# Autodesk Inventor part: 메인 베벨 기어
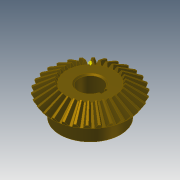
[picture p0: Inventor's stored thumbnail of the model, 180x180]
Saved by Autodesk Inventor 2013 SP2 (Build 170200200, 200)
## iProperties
Created: 2014-10
Part Number: 메인 베벨 기어
Material: Steel, Mild
Document SubType Name: Modeling
Designer: KYOUNG IL JANG
Categories: <?xml version="1.0" encoding="UTF-16"?> <MemberInstance><Categories><FamilyTemplate><FamilyTemplateParameter ValueType="xs:double" Id="1" ObjectReferenceKey="da
Mass: 269.583 g
Surface Area: 108.837 cm^2
Volume: 34.2981 cm^3
Density: 7.86 g/cm^3
CustomPartVersion: 1
Company: 한국ATC센터
Author: KYOUNG IL JANG
Revision Number: 1
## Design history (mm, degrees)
node "맨 위 점"
node "메쉬 평면2"
sketch "톱니 본체 스케치"
  geometry: L1 (0, 0)-(28.669, -21.997); L2 (28.669, -21.997)-(31.109, -18.336); L3 (31.109, -18.336)-(0, 0); L4 (30, -20)-(0, 0); L5 (17.219, -13.212)-(18.685, -11.013); L6 (28.669, -21.997)-(17.219, -13.212); L7 (31.109, -18.336)-(18.685, -11.013); L8 (0, -39.387)-(0, 6.564) reference; L9 (0, -20)-(31.109, -20)
  constraints: 16 end point, 4 point on line, 3 perpendicular, 2 collinear, 1 horizontal alignment, 1 vertical alignment
  dimensions: "d0" = 60 diameter of L4.start L8 (= da_de); "d1" = 57.33744 diameter of L1.end L8 (= da_dfe); "d2" = 62.2188 diameter of L2.end L8 (= da_dae); "d3" = 14.4 distance between parallel lines of L2 L5 (= da_b); "d4" = 18.3359 vertical distance of L2.end L1.start (= da_ve)
revolve "톱니 본체" sketch "톱니 본체 스케치" stored, may be unused: angle "d5" = 90 deg
node "시작점"
node "톱니 평면"
sketch "시작 스케치"
  geometry: L1 (0, -23.505)-(0, 10.645) reference; L2 (-0.709, -2.928)-(0.709, -2.928); A1 r 19.188 centre (-19.457, -7.014) between (-0.709, -2.928) and (-3.232, 3.229); A2 r 19.188 centre (19.457, -7.014) between (3.232, 3.229) and (0.709, -2.928); A3 r 57.403 centre (0, -54.083) between (3.232, 3.229) and (-3.232, 3.229); 1 further point
  constraints: 6 point on circle, 3 centre point, 3 symmetric about line, 2 end point, 1 coincident, 1 perpendicular, 1 other
  dimensions: "d7" = 19.18795 radius of A1 (= fd_rr); "d8" = 19.45712 horizontal distance of point (0, -54.083) A1.centre (= fd_x); "d9" = 47.06905 vertical distance of point (0, -54.083) A1.centre (= fd_y); "d57" = 57.40327 radius of A3 (= 0.5 x fd_dva + 0.3 x da_he); "d58" = 51.15527 distance from line of A3.centre L2 (= 0.5 x fd_dva - 1.12 x da_he)
node "끝점"
  node "끝 평면"
sketch "3D 스케치 오른쪽"
  node "Helical Curve Right" dims "d65" = 229.90621 (computed from da_dm, da_delta, da_beta), "d66" = 31.5, "d67" = 60 (= da_de), "d68" = -9.82794 (= -da_delta), "d69" = 8.10972 (computed from fd_loft, da_delta)
node "끝 평면 오른쪽"
sketch "끝 스케치 오른쪽"
  geometry: L1 (0, -41.54)-(0, 13.178) reference; L2 (-0.422, -1.69)-(0.422, -1.69); A1 r 11.427 centre (-11.587, -4.123) between (-0.422, -1.69) and (-1.925, 1.977); A2 r 11.427 centre (11.587, -4.123) between (1.925, 1.977) and (0.422, -1.69); A3 r 34.184 centre (0, -32.153) between (1.925, 1.977) and (-1.925, 1.977); 1 further point
  constraints: 6 point on circle, 3 centre point, 3 symmetric about line, 2 end point, 1 coincident, 1 perpendicular, 1 other
  dimensions: "d70" = 11.58699 horizontal distance of A3.centre A1.centre (computed from fd_x, fd_ratio); "d71" = 28.03028 vertical distance of point (0, -32.153) A1.centre (computed from fd_y, fd_ratio); "d72" = 11.4267 radius of A1 (computed from fd_rr, fd_ratio); "d73" = 30.46369 distance from line of point (0, -32.153) L2 (computed from d58, fd_ratio); "d74" = 34.18446 radius of A3 (computed from d57, fd_ratio)
feature "로프트 오른쪽" sketch "끝 스케치 오른쪽" dims "d75" = 0, "d77" = 0, "d79" = 0, "d80" = 90 deg, "d85" = 20, "d92" = 90 deg, "d93" = 90 deg, "da_teethtype" = 0 [user parameter]
sketch "3D 스케치 왼쪽"
  node "Helical Curve Left" dims "d26" = 229.90621 (computed from da_dm, da_delta, da_beta), "d27" = 8.10972 (computed from fd_loft, da_delta), "d28" = 60 (= da_de), "d29" = -9.82794 (= -da_delta)
node "끝 평면 왼쪽"
sketch "끝 스케치 왼쪽" dims "d56" = 10.3728 (derived)
  geometry: L1 (0, -43.753)-(0, 15.405) reference; L2 (-0.422, -1.678)-(0.422, -1.678); A1 r 11.427 centre (-11.587, -4.111) between (-0.422, -1.678) and (-1.925, 1.988); A2 r 11.427 centre (11.587, -4.111) between (1.925, 1.988) and (0.422, -1.678); A3 r 34.184 centre (0, -32.142) between (1.925, 1.988) and (-1.925, 1.988); 2 further points; 1 other entity
  constraints: 6 point on circle, 3 centre point, 3 symmetric about line, 2 end point, 1 coincident, 2 other
  dimensions: "d30" = 11.4267 radius of A1 (computed from fd_rr, fd_ratio); "d31" = 11.58699 horizontal distance of point (0, -32.142) A1.centre (computed from fd_x, fd_ratio); "d32" = 28.03028 vertical distance of A1.centre point (0, -32.142) (computed from fd_y, fd_ratio); "d61" = 34.18446 radius of A3 (computed from d57, fd_ratio); "d62" = 30.46369 distance from line of point (0, -32.142) L2 (computed from d58, fd_ratio)
feature "로프트 왼쪽" sketch "끝 스케치 왼쪽" dims "d35" = 0, "d37" = 0, "d39" = 0, "d40" = 90 deg, "d84" = 10, "d90" = 90 deg, "d91" = 90 deg, "da_teethtype" = 0 [user parameter]
sketch "본체 스케치"
  geometry: L1 (0, -35.038)-(0, -19.531) reference; L2 (28.669, -21.997)-(17.219, -13.212) reference; L3 (17.219, -13.212)-(0, -13.212); L4 (28.669, -21.997)-(0, -21.997)
  constraints: 4 end point, 2 perpendicular, 2 point on line
revolve "본체 고정" sketch "본체 스케치" stored, may be unused: angle "d46" = 90 deg
feature "피치 지름" dims angle "d47" = 90 deg
sketch "스케치8"
  geometry: C1 r 22.5 at (0, 0); 1 further point
  constraints: 1 centre point, 1 coincident
  dimensions: "d94" = 45 diameter of C1
extrude "돌출1" join sketch "스케치8" distance "d95" = 13; taper "d96" = 0 deg
sketch "스케치9"
  geometry: 1 further point
hole "구멍1" sketch "스케치9" at (0, 0) diameter "d97" = 17; stored, may be unused: countersink angle "d101" = 90 deg, drill point angle "d103" = 118 deg; dims "d98" = 6, "d99" = 4, "d100" = 2, "d102" = 8
sketch "스케치10"
  geometry: L1 (8.124, 2.5)-(10.8, 2.5); L2 (10.8, 2.5)-(10.8, -2.5); L3 (10.8, -2.5)-(8.124, -2.5); A1 r 8.5 centre (0, 0) between (8.124, 2.5) and (8.124, -2.5) reference; 1 further point
  constraints: 6 end point, 2 parallel, 2 point on circle, 1 horizontal, 1 perpendicular
  dimensions: "d104" = 5 distance of L1.end L2.end; "d112" = 19.3 dimension on A1 L2
extrude "돌출2" cut sketch "스케치10" stored distance "d106" = 10; taper "d107" = 0 deg
chamfer "모따기1" distance "d108" = 1; stored, may be unused: second distance "d109" = 2, angle "d110" = 45 deg
fillet "모깎기1" dims "d111" = 2
body "Solid1"
feature "로프트" dims "d17" = 0, "d18" = 90 deg, "d19" = 0, "d20" = 90 deg, "d89" = 0, "da_teethtype" = 0 [user parameter]
pattern_circular "원형 패턴" dims angle "d22" = 360 deg, "d88" = 0, "da_teethtype" = 0 [user parameter]
pattern_circular "원형 패턴 오른쪽" dims angle "d82" = 360 deg, "da_teethtype" = 0 [user parameter]
pattern_circular "원형 패턴 왼쪽" dims angle "d42" = 360 deg, "da_teethtype" = 0 [user parameter]
sketch "끝 스케치"
  geometry: L1 (0, -15.359)-(0, 6.983) reference; L2 (-0.422, -1.69)-(0.422, -1.69); A1 r 11.427 centre (-11.587, -4.123) between (-0.422, -1.69) and (-1.925, 1.977); A2 r 11.427 centre (11.587, -4.123) between (1.925, 1.977) and (0.422, -1.69); A3 r 34.184 centre (0, -32.153) between (1.925, 1.977) and (-1.925, 1.977); 1 further point
  constraints: 6 point on circle, 3 centre point, 3 symmetric about line, 2 end point, 1 coincident, 1 other
  dimensions: "d12" = 11.4267 radius of A1 (computed from fd_rr, fd_ratio); "d15" = 11.58699 horizontal distance of A1.centre point (0, -32.153) (computed from fd_x, fd_ratio); "d16" = 28.03028 vertical distance of A1.centre point (0, -32.153) (computed from fd_y, fd_ratio); "d59" = 34.18446 radius of A3 (computed from d57, fd_ratio); "d60" = 30.46369 distance from line of A3.centre L2 (computed from d58, fd_ratio)
sketch "Sketch6"
  geometry: L1 (30, -20)-(0, 0) reference; L2 (0, -37.8)-(0, 6.3) reference
body "Srf1"
other parameters: "da_b" = 14.4 [user parameter; used in 2 equation terms], "da_de" = 60 [user parameter; used in 4 equation terms], "da_dae" = 62.2188 [user parameter; used in 2 equation terms], "da_dfe" = 57.33744 [user parameter; used in 1 equation term], "da_le" = 36.05551 [user parameter; used in 1 equation term], "da_omega" = 90 deg [user parameter; used in 1 equation term], "da_beta" = 0 [user parameter; used in 2 equation terms], "da_delta" = 9.82794 [user parameter; used in 8 equation terms], "da_alpha" = 20 deg [user parameter; used in 2 equation terms], "da_he" = 4.4 [user parameter; used in 4 equation terms], "da_ve" = 18.3359 [user parameter; used in 1 equation term], "fd_dv" = 108.16654 (computed from da_de, da_delta) [user parameter; used in 1 equation term], "fd_dva" = 112.16654 (computed from da_dae, da_delta) [user parameter; used in 3 equation terms], "fd_dvb" = 101.6433 (computed from fd_dv, da_alpha) [user parameter; used in 2 equation terms], "da_zv" = 540.83269 [user parameter; used in 1 equation term], "fd_loft" = 14.62 (= da_b + 0.05 x da_he) [user parameter; used in 4 equation terms], "fd_ratio" = 5.95514 (computed from da_le, fd_loft) [user parameter; used in 15 equation terms], "fd_rr" = 19.18795 (computed from fd_dd, fd_dvb) [user parameter; used in 6 equation terms], "fd_angle" = 0.29367 (computed from da_zv) [user parameter; used in 4 equation terms], "fd_x1" = 1.58802 (computed from da_dvw, fd_angle) [user parameter; used in 1 equation term], "fd_y1" = 54.05995 (computed from da_dvw, fd_angle) [user parameter; used in 1 equation term], "fd_x2" = 17.8691 (computed from fd_rr, fd_angle2, fd_angle) [user parameter; used in 1 equation term], "fd_y2" = 6.9909 (computed from fd_rr, fd_angle2, fd_angle) [user parameter; used in 1 equation term], "fd_x" = 19.45712 (= fd_x1 + fd_x2) [user parameter; used in 4 equation terms], "fd_y" = 47.06905 (= fd_y1 - fd_y2) [user parameter; used in 4 equation terms], "fd_angle2" = 3.43555 (computed from fd_dvb, fd_dd, da_alpha) [user parameter; used in 2 equation terms], "fd_dd" = 108.64654 (= fd_dva - 0.8 x da_he) [user parameter; used in 2 equation terms], "da_dvw" = 108.16654 [user parameter; used in 2 equation terms], "d11" = 14.62 (= fd_loft), "da_dm" = 48.01848 [user parameter; used in 2 equation terms], "da_x" = 0 [user parameter], "da_m" = 2 [user parameter], "d48" = 0, "d49" = 0, "d50" = 90 deg (= da_omega), "d51" = 6 deg (computed from da_z), "d52" = 0, "d53" = 0, "d54" = 0
